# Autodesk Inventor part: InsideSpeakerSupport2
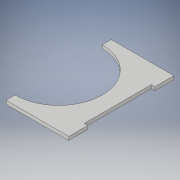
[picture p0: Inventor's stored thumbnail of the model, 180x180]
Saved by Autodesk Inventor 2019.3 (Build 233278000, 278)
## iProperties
Created: 2020-02
Part Number: InsideSpeakerSupport2
Material: Generic
Document SubType Name: Modeling
Designer: KrystynWikoff
Density: 1 g/cm^3
Appearance: Default
Author: KrystynWikoff
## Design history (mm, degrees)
sketch "Sketch1"
  geometry: L1 (0, 0)-(41.732, 0); L2 (41.732, 0)-(41.732, -70); L3 (41.732, -70)-(0, -70); L4 (0, -70)-(0, 0)
  constraints: 8 end point, 2 parallel, 1 horizontal, 1 perpendicular
  dimensions: "d0" = 70 distance of L3.end L1.start; "d1" = 41.7322 distance of L1.start L1.end
extrude "Extrusion1" new body sketch "Sketch1" distance "d2" = 2.3622; taper "d3" = 0 deg
sketch "Sketch2"
  geometry: L1 (-41.732, 70)-(-41.732, 0) reference; L2 (-41.732, 0)-(0, 0) reference; L3 (0, 0)-(0, 70) reference; L4 (0, 12.7)-(-2.362, 12.7); L5 (-2.362, 12.7)-(-2.362, 57.3); L6 (-2.362, 57.3)-(0, 57.3); L7 (0, 57.3)-(0, 12.7); L8 (0, 70)-(-41.732, 70) reference; C1 r 29 at (-41.732, 35)
  constraints: 8 end point, 2 parallel, 1 centre point, 1 horizontal, 1 midpoint, 1 perpendicular, 1 point on line
  dimensions: "d4" = 35 distance from line of L2 C1.centre; "d5" = 58 diameter of C1; "d6" = 12.7 distance between parallel lines of L2 L4; "d7" = 2.3622 distance of L5.end L6.end; "d8" = 12.7 distance between parallel lines of L8 L6
extrude "Extrusion2" cut sketch "Sketch2" distance "d9" = 2.3622; taper "d10" = 0 deg
body "Solid1"
